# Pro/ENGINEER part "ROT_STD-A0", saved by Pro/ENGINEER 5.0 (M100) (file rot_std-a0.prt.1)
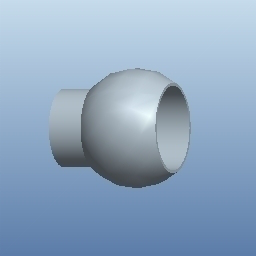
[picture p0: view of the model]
Units: millimeter Newton Second (mmNs); MM, TONNE, SECS

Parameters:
  MERGE_BASE_PART = "80025000-ROTULE_STD_A0"

Other named items: DROITE, DESSUS, FACE, 80025000-ROTULE_STD_01_1, O_R

Layers: 02_POINTS, 03_PLANS, 05_SURFACES, 06_REPERES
